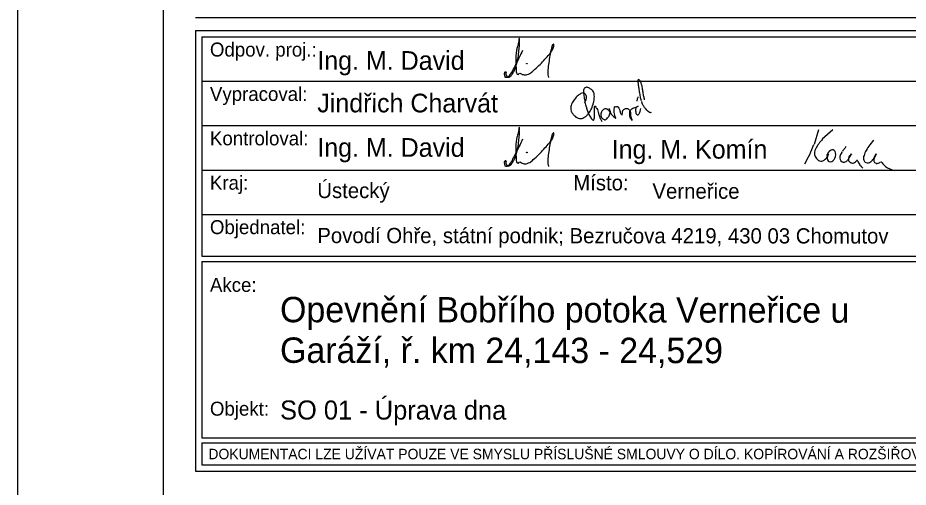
# Model space of a CAD drawing. Extents: x 67.3 to 115.4, y -93.9 to -78.3.
# Drawn here: x 79.77 to 86.79, y -86.38 to -82.68 of the extents above; entities that cross this region are included whole.
import ezdxf

# ---------------------------------------------------------------- set-up
doc = ezdxf.new("R2010")
doc.units = 0
for name, color, linetype in [('07_rozpiska', 7, 'Continuous'), ('07_rámeček', 7, 'Continuous'), ('Default', 7, 'Continuous'), ('Rozpiska + rámeček', 7, 'Continuous')]:
    doc.layers.add(name, color=color, linetype=linetype)

# ---------------------------------------------------------------- blocks, each defined once
blk = doc.blocks.new('Charvat')
at = {"layer": 'Rozpiska + rámeček'}
for points in [[(0.0826, 0.02), (0.0817, 0.0228), (0.0806, 0.0281), (0.0796, 0.0345), (0.0789, 0.0395), (0.0784, 0.0445), (0.0784, 0.0456), (0.0785, 0.0469), (0.0787, 0.0476), (0.0791, 0.0473), (0.0804, 0.0456), (0.0816, 0.0427), (0.0827, 0.0394), (0.0832, 0.0363), (0.0841, 0.0314), (0.0846, 0.0282), (0.0855, 0.0238), (0.086, 0.0216)], [(0.0108, 0.0178), (0.0123, 0.0208), (0.0129, 0.0234), (0.0122, 0.0279), (0.0108, 0.0294), (0.0087, 0.0301), (0.0059, 0.0293), (0.0024, 0.0271), (-0.0017, 0.0225), (-0.0049, 0.0177), (-0.0062, 0.0145), (-0.0067, 0.0115), (-0.0063, 0.0075), (-0.0059, 0.0064), (-0.0039, 0.0034), (-0.0014, 0.0007), (0.001, -0.001), (0.0043, -0.0019), (0.0075, -0.0019), (0.0097, -0.001), (0.0131, 0.0013), (0.0158, 0.0045), (0.0192, 0.0101), (0.022, 0.0182), (0.0223, 0.0193), (0.023, 0.0256), (0.0227, 0.0293), (0.0219, 0.0315), (0.0199, 0.034), (0.017, 0.036), (0.0147, 0.0371), (0.0142, 0.0372), (0.013, 0.0373), (0.0113, 0.0368), (0.0106, 0.0362), (0.0097, 0.0348), (0.0095, 0.0343), (0.0093, 0.0333), (0.0093, 0.0314), (0.0096, 0.0279), (0.0105, 0.0221), (0.012, 0.0151), (0.0133, 0.0108), (0.0166, 0.0023), (0.0195, -0.0026), (0.0202, -0.0035), (0.0214, -0.0042), (0.022, -0.0042), (0.0225, -0.0034), (0.023, -0.0014), (0.0231, 0), (0.0231, 0.0051), (0.0231, 0.0111), (0.0231, 0.0124), (0.0233, 0.0132), (0.0236, 0.0135), (0.024, 0.0133), (0.0254, 0.0115), (0.0268, 0.0092), (0.0279, 0.0059), (0.0289, 0.0018), (0.0298, -0.0012), (0.0315, -0.0041), (0.0327, -0.0059)], [(0.0771, 0.0198), (0.0779, 0.024), (0.0784, 0.0252)], [(0.0428, 0.0062), (0.0417, 0.0075), (0.0401, 0.009), (0.0394, 0.0095), (0.0378, 0.0101), (0.0368, 0.0101), (0.0353, 0.0098), (0.034, 0.0088), (0.0326, 0.0071), (0.0316, 0.0051), (0.0313, 0.0026), (0.0313, 0.0011), (0.0322, -0.0007), (0.0338, -0.0025), (0.0354, -0.0034), (0.0366, -0.0037), (0.0381, -0.0031), (0.0397, -0.0014), (0.0411, 0.0004), (0.0422, 0.0025), (0.043, 0.005), (0.043, 0.0063), (0.0429, 0.0069), (0.0424, 0.0086), (0.0414, 0.0106), (0.0421, 0.009), (0.0433, 0.0053), (0.0444, 0.0034), (0.0458, 0.0017), (0.0476, 0), (0.0497, -0.0015), (0.0498, -0.0016), (0.0499, -0.0016), (0.0499, -0.0014), (0.0492, 0.0003), (0.0487, 0.0022), (0.0482, 0.0055), (0.048, 0.0086), (0.0484, 0.0114), (0.0491, 0.0131), (0.0493, 0.013), (0.0506, 0.0127), (0.0522, 0.0131), (0.0539, 0.0111), (0.0547, 0.0094), (0.0552, 0.0074), (0.0556, 0.0056), (0.0566, 0.0038), (0.058, 0.0025), (0.0582, 0.0031), (0.0585, 0.0057), (0.0589, 0.0076), (0.0593, 0.0083), (0.0604, 0.0095), (0.0616, 0.0102), (0.0632, 0.0106), (0.065, 0.0106), (0.0665, 0.0094), (0.0678, 0.0078), (0.0686, 0.0033), (0.0691, 0.0001), (0.0701, -0.0031), (0.0705, -0.0044), (0.0697, -0.0035), (0.0682, -0.0005), (0.0677, 0.0025), (0.0677, 0.0059), (0.0683, 0.0079), (0.0702, 0.01), (0.0728, 0.0114), (0.0756, 0.0122), (0.0781, 0.0133), (0.0764, 0.0125), (0.0755, 0.0112), (0.0751, 0.0096), (0.0751, 0.0075), (0.0753, 0.005), (0.0753, 0.0048), (0.0758, 0.0038), (0.0766, 0.003), (0.0772, 0.0026), (0.0776, 0.0025), (0.0783, 0.0027), (0.0791, 0.0034), (0.0799, 0.0047), (0.0806, 0.0069), (0.0816, 0.0104)], [(0.0947, 0.0053), (0.0934, 0.0053), (0.0921, 0.0059), (0.0901, 0.0076), (0.0883, 0.0095), (0.0858, 0.0127), (0.0839, 0.0159), (0.0829, 0.0186), (0.0827, 0.0193)]]:
    blk.add_spline(points, degree=3, dxfattribs=at)

msp = doc.modelspace()

# ---------------------------------------------------------------- linework, layer by layer
at = {"layer": '07_rozpiska'}
msp.add_line((89.7689, -82.6813), (81.1689, -82.6813), dxfattribs=at)
for points in [[(83.7239, -82.8729), (83.7252, -82.8631), (83.7246, -82.8434), (83.7168, -82.8742), (83.7064, -82.9163), (83.7003, -82.9425), (83.6971, -82.9862), (83.6954, -83.0219), (83.6987, -83.0964), (83.7019, -83.1161), (83.7145, -83.1278), (83.7191, -83.1246), (83.7201, -83.1223), (83.7272, -83.1174), (83.7398, -83.1239), (83.7534, -83.1294), (83.7683, -83.132), (83.7865, -83.1291), (83.8069, -83.1207), (83.8334, -83.0993), (83.8772, -83.0582), (83.9173, -83.017), (83.9513, -82.9785), (83.9789, -82.9451), (83.9938, -82.9121), (83.9973, -82.8959), (83.996, -82.8891), (83.9899, -82.8904), (83.9792, -82.9137), (83.9734, -82.9376), (83.9646, -82.9794), (83.9559, -83.0351), (83.9488, -83.0912), (83.9481, -83.12), (83.9517, -83.1417), (83.9536, -83.1524)], [(83.7178, -82.9781), (83.7197, -82.9522), (83.7223, -82.9296), (83.7243, -82.9053), (83.7239, -82.8729)], [(83.6093, -83.1333), (83.6073, -83.1216), (83.6083, -83.1139), (83.6132, -83.1074), (83.6167, -83.1067), (83.6187, -83.1187), (83.6193, -83.133), (83.6274, -83.1453), (83.6387, -83.1495), (83.6494, -83.1456), (83.6588, -83.1378), (83.664, -83.131), (83.6792, -83.1067), (83.6854, -83.0951), (83.7013, -83.0488), (83.7178, -82.9781)], [(83.7502, -82.9386), (83.7226, -82.9934), (83.6763, -83.0854), (83.643, -83.1398), (83.6306, -83.1511), (83.6213, -83.1527), (83.6154, -83.1521), (83.6112, -83.1453), (83.6093, -83.1333)], [(83.7826, -83.0403), (83.7803, -83.0413), (83.7803, -83.0433), (83.7819, -83.0442), (83.7852, -83.0449), (83.7858, -83.0433), (83.7858, -83.0416), (83.7826, -83.0403)], [(83.7239, -83.5729), (83.7252, -83.5631), (83.7246, -83.5434), (83.7168, -83.5742), (83.7064, -83.6163), (83.7003, -83.6425), (83.6971, -83.6862), (83.6954, -83.7219), (83.6987, -83.7964), (83.7019, -83.8161), (83.7145, -83.8278), (83.7191, -83.8246), (83.7201, -83.8223), (83.7272, -83.8174), (83.7398, -83.8239), (83.7534, -83.8294), (83.7683, -83.832), (83.7865, -83.8291), (83.8069, -83.8207), (83.8334, -83.7993), (83.8772, -83.7582), (83.9173, -83.717), (83.9513, -83.6785), (83.9789, -83.6451), (83.9938, -83.6121), (83.9973, -83.5959), (83.996, -83.5891), (83.9899, -83.5904), (83.9792, -83.6137), (83.9734, -83.6376), (83.9646, -83.6794), (83.9559, -83.7351), (83.9488, -83.7912), (83.9481, -83.82), (83.9517, -83.8417), (83.9536, -83.8524)], [(83.7178, -83.6781), (83.7197, -83.6522), (83.7223, -83.6296), (83.7243, -83.6053), (83.7239, -83.5729)], [(83.6093, -83.8333), (83.6073, -83.8216), (83.6083, -83.8139), (83.6132, -83.8074), (83.6167, -83.8067), (83.6187, -83.8187), (83.6193, -83.833), (83.6274, -83.8453), (83.6387, -83.8495), (83.6494, -83.8456), (83.6588, -83.8378), (83.664, -83.831), (83.6792, -83.8067), (83.6854, -83.7951), (83.7013, -83.7488), (83.7178, -83.6781)], [(83.7502, -83.6386), (83.7226, -83.6934), (83.6763, -83.7854), (83.643, -83.8398), (83.6306, -83.8511), (83.6213, -83.8527), (83.6154, -83.8521), (83.6112, -83.8453), (83.6093, -83.8333)], [(83.7826, -83.7403), (83.7803, -83.7413), (83.7803, -83.7433), (83.7819, -83.7442), (83.7852, -83.7449), (83.7858, -83.7433), (83.7858, -83.7416), (83.7826, -83.7403)]]:
    msp.add_spline(points, degree=3, dxfattribs=at)
at = {"layer": 'Default'}
for p, q in [((86.1487, -83.7799), (86.1631, -83.754)), ((86.3906, -83.8087), (86.4007, -83.826)), ((86.4223, -83.8548), (86.4338, -83.8663))]:
    msp.add_line(p, q, dxfattribs=at)
for points in [[(86.0839, -83.5639), (86.0479, -83.6791)], [(86.1962, -83.5639), (86.1127, -83.6388)], [(86.2999, -83.6964), (86.2898, -83.7108)], [(86.5159, -83.646), (86.4871, -83.682)], [(86.2711, -83.7367), (86.2682, -83.7396)], [(86.3359, -83.7655), (86.3431, -83.754), (86.333, -83.7655)], [(86.513, -83.7972), (86.5375, -83.754), (86.5274, -83.7799)], [(86.3186, -83.7972), (86.3186, -83.7972)], [(86.3215, -83.7799), (86.3215, -83.7828)]]:
    msp.add_lwpolyline(points, dxfattribs=at)
for centre, radius, start, end in [((85.1146, -83.3324), 0.9948, 329.80858, 339.56815), ((86.3727, -83.8806), 0.3545, 137.00062, 151.51062), ((86.7188, -83.8677), 0.2956, 141.11668, 151.43002), ((86.125, -83.7472), 0.0732, 150.83631, 201.23374), ((86.2259, -83.7954), 0.084, 133.12102, 160.6603), ((86.2051, -83.7877), 0.0529, 142.82783, 193.29225), ((86.3568, -83.8022), 0.1085, 146.31446, 165.71836), ((86.0269, -83.5822), 0.288, 326.31446, 326.46946), ((86.5115, -83.8936), 0.288, 140.57196, 146.46893), ((86.168, -83.6865), 0.1862, 320.58833, 335.16259), ((86.3745, -83.804), 0.0576, 139.19606, 154.94016), ((86.4996, -83.7884), 0.0617, 158.78845, 195.14726), ((86.6405, -83.8271), 0.2075, 150.931, 162.8917), ((86.1315, -83.7376), 0.083, 205.78195, 234.22418), ((86.1031, -83.774), 0.0369, 236.98468, 294.62862), ((86.143, -83.8912), 0.0864, 108.04736, 108.08265), ((86.0807, -83.7298), 0.0864, 295.93387, 323.63221), ((86.2835, -83.7872), 0.0323, 245.35778, 276.92267), ((86.2765, -83.7731), 0.0475, 283.31943, 318.16716), ((86.3473, -83.7942), 0.0288, 154.94151, 187.17365), ((86.3473, -83.7955), 0.0286, 186.45097, 212.31824), ((86.3506, -83.7936), 0.0324, 212.08411, 258.70933), ((86.3522, -83.79), 0.0362, 257.35338, 296.27075), ((86.3458, -83.7858), 0.043, 301.37529, 327.02531), ((86.3869, -83.8121), 0.00576, 26.63136, 150.41952), ((86.4782, -83.7885), 0.0864, 206.63144, 229.82938), ((86.4654, -83.7965), 0.0265, 197.61582, 249.38851), ((86.4718, -83.7778), 0.0463, 250.12564, 275.82035), ((86.4725, -83.789), 0.035, 276.59581, 304.89281), ((86.4307, -83.7405), 0.099, 308.6573, 325.5075), ((86.5479, -83.8029), 0.0297, 172.16185, 218.17447), ((86.5848, -83.8117), 0.0677, 151.17648, 169.00349), ((86.547, -83.7945), 0.0349, 229.93747, 256.22885), ((86.5432, -83.7829), 0.0458, 264.36538, 302.31991), ((86.5747, -83.8331), 0.0136, 38.96313, 121.674), ((86.6941, -83.7484), 0.1329, 214.99845, 231.36881), ((86.7307, -83.6828), 0.2073, 234.79421, 256.99308)]:
    msp.add_arc(centre, radius, start, end, dxfattribs=at)
for centre, major_axis, ratio, start_param, end_param in [((86.1846, -83.7696), (0.0152, 0.0459), 0.677007, 2.488228, 7.220838), ((86.2873, -83.7863), (-0.0357, 0.0109), 0.932374, 0, 1.363098)]:
    msp.add_ellipse(centre, major_axis=major_axis, ratio=ratio, start_param=start_param, end_param=end_param, dxfattribs=at)
at = {"layer": 'Rozpiska + rámeček'}
for p, q in [((81.1689, -82.7813), (81.1689, -86.2563)), ((81.1689, -82.7813), (89.7689, -82.7813)), ((81.2189, -82.8313), (81.2189, -84.5613)), ((81.2189, -82.8313), (86.8789, -82.8313)), ((81.2189, -83.1813), (86.8789, -83.1813)), ((81.2189, -83.5313), (86.8789, -83.5313)), ((81.2189, -83.8813), (86.8789, -83.8813)), ((81.2189, -84.2313), (86.8789, -84.2313)), ((81.2189, -84.5613), (86.8789, -84.5613)), ((81.2189, -84.6013), (86.8789, -84.6013)), ((81.2189, -84.6013), (81.2189, -85.9913)), ((81.2189, -85.9913), (86.8789, -85.9913)), ((81.2189, -86.0313), (89.7189, -86.0313)), ((81.2189, -86.0313), (81.2189, -86.2063)), ((81.2189, -86.2063), (89.7189, -86.2063)), ((81.1689, -86.2563), (89.7689, -86.2563))]:
    msp.add_line(p, q, dxfattribs=at)
for points in [[(79.7689, -79.0813), (90.2689, -79.0813), (90.2689, -93.9313), (79.7689, -93.9313)], [(80.9189, -79.0813), (90.0189, -79.0813), (90.0189, -86.5063), (80.9189, -86.5063)]]:
    msp.add_lwpolyline(points, close=True, dxfattribs=at)

# ---------------------------------------------------------------- block references
at = {"layer": '07_rámeček', "xscale": 6.250000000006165, "yscale": 6.250000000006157, "rotation": 3.739011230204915e-09}
msp.add_blockref('Charvat', (84.1718, -83.462), dxfattribs=at)

# ---------------------------------------------------------------- texts
at = {"layer": '07_rozpiska'}
for s, height, p in [('Opevnění Bobřího potoka Verneřice u ', 0.2, (81.8369, -85.0811)), ('Garáží, ř. km 24,143 - 24,529', 0.2, (81.8366, -85.4011)), ('SO 01 - Úprava dna', 0.15, (81.8369, -85.8476))]:
    msp.add_text(s, height=height, rotation=359.95393, dxfattribs=at).set_placement(p)
at = {"layer": 'Rozpiska + rámeček'}
for s, height, rotation, p in [('Odpov. proj.:', 0.11, 359.95393, (81.2839, -82.9863)), ('Ing. M. David', 0.147465, 359.95278, (82.1306, -83.0907)), ('Vypracoval:', 0.11, 359.95393, (81.2839, -83.3363)), ('Jindřich Charvát', 0.147465, 359.95278, (82.1306, -83.4263)), ('Kontroloval:', 0.11, 359.95393, (81.2839, -83.6863)), ('Ing. M. David', 0.147465, 359.95278, (82.1306, -83.7763)), ('Ing. M. Komín', 0.147465, 359.95278, (84.4523, -83.7907)), ('Kraj:', 0.11, 359.95393, (81.2839, -84.0363)), ('Ústecký', 0.12, 359.95393, (82.1306, -84.1023)), ('Místo:', 0.12, 359.95393, (84.1489, -84.0413)), ('Verneřice', 0.12, 359.95278, (84.7738, -84.1071)), ('Objednatel:', 0.11, 359.95393, (81.2839, -84.3863)), ('Povodí Ohře, státní podnik; Bezručova 4219, 430 03 Chomutov', 0.12, 359.95278, (82.1306, -84.4571)), ('Akce:', 0.11, 359.95393, (81.2839, -84.8413)), ('Objekt:', 0.11, 359.95393, (81.2839, -85.8174))]:
    msp.add_text(s, height=height, rotation=rotation, dxfattribs=at).set_placement(p)
msp.add_text('DOKUMENTACI LZE UŽÍVAT POUZE VE SMYSLU PŘÍSLUŠNÉ SMLOUVY O DÍLO. KOPÍROVÁNÍ A ROZŠIŘOVÁNÍ POUZE PO PŘEDCHOZÍM SOUHLASU  AZ CONSULT spol. s. r.o.', height=0.0822563, dxfattribs=at).set_placement((81.2718, -86.1609))

doc.saveas('drawing.dxf')
